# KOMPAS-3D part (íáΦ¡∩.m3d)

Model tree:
1. Эскиз:1
2. Смещенная плоскость:28
     Расстояние = 5.4
3. Смещенная плоскость:29
     Расстояние = 5.4
4. Смещенная плоскость:30
     Расстояние = 5.4
5. Смещенная плоскость:31
     Расстояние = 5.4
6. Смещенная плоскость:32
     Расстояние = 5.4
7. Смещенная плоскость:33
     Расстояние = 5.4
8. Смещенная плоскость:34
     Расстояние = 5.4
9. Эскиз:10
10. Эскиз:11
11. Эскиз:12
12. Эскиз:13
13. Эскиз:14
14. Эскиз:15
15. Эскиз:16
16. Поверхность по сечениям:12
     Толщина стенки 1 = 1; Толщина стенки 2 = 1
17. Заплатка:3
18. Сшивка поверхностей:6
     Точность сшивки = 0.01
19. Придать толщину:8
     Толщина стенки 1 = 1; Толщина стенки 2 = 1
20. Эскиз:43
21. Операция выдавливания:5
     Расстояние 1 = 13; Расстояние 2 = 5
22. Эскиз:44
23. Вырезать элемент выдавливания:11
     Расстояние 1 = 20
24. Скругление:6
     Радиус = 1
25. Скругление:8
     Радиус = 1
26. Эскиз:45
27. Вырезать элемент выдавливания:12
     Расстояние 2 = 20; Расстояние 1 = 20
28. Эскиз:46
29. Вырезать элемент выдавливания:13
     Расстояние 2 = 40; Расстояние 1 = 0.0231076
30. Скругление:9
     Радиус = 0.2
31. Эскиз:47
32. Вырезать элемент выдавливания:14
     Расстояние 2 = 40; Расстояние 1 = 0.755166
33. Заплатка:9
34. Придать толщину:11
     Толщина стенки 1 = 1.8; Толщина стенки 2 = 1
35. Заплатка:10
36. Придать толщину:12
     Толщина стенки 1 = 1.8; Толщина стенки 2 = 1

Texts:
  Сплав АЛ8  ГОСТ 1583-93
  stalker61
